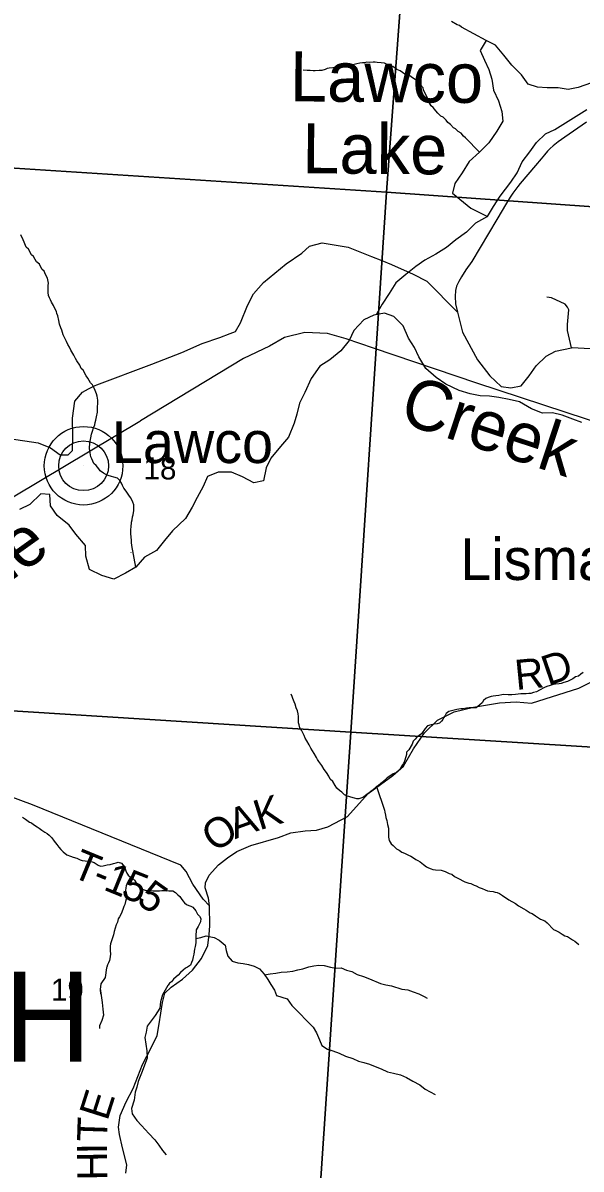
# Model space of a CAD drawing. Extents: x 0 to 34, y 0 to 22.
# Drawn here: x 6.769 to 7.827, y 16.547 to 18.72 of the extents above; entities that cross this region are included whole.
import ezdxf

# ---------------------------------------------------------------- set-up
doc = ezdxf.new("R2010")
doc.units = 0
for name, color, linetype in [('GM_X_County_Road', 7, 'Continuous'), ('GM_X_County_Road_Text', 7, 'Continuous'), ('GM_X_Minor_Lake', 7, 'Continuous'), ('GM_X_Minor_Lake_Text', 7, 'Continuous'), ('GM_X_Minor_River', 7, 'Continuous'), ('GM_X_Minor_River_Text', 7, 'Continuous'), ('GM_X_Rail_Line', 7, 'Continuous'), ('GM_X_Section', 7, 'Continuous'), ('GM_X_Section_Text', 7, 'Continuous'), ('GM_X_State_Route', 7, 'Continuous'), ('GM_X_Township_Road', 7, 'Continuous'), ('GM_X_Township_Road_Text', 7, 'Continuous'), ('GM_X_Township_Text', 7, 'Continuous'), ('GM_X_Unincorporated', 7, 'Continuous'), ('GM_X_Unincorporated_Location', 7, 'Continuous'), ('GM_X_Unincorporated_Text', 7, 'Continuous')]:
    doc.layers.add(name, color=color, linetype=linetype)

msp = doc.modelspace()

# ---------------------------------------------------------------- linework, layer by layer
at = {"layer": 'GM_X_County_Road'}
for points in [[(6.9065, 18.0325), (6.9091, 18.0338), (7.0137, 18.0729), (7.0705, 18.095), (7.1092, 18.112), (7.1425, 18.1234), (7.1622, 18.1306), (7.1721, 18.1348), (7.1816, 18.1511), (7.1948, 18.1841), (7.2062, 18.2058), (7.2251, 18.2278), (7.2679, 18.2627), (7.2979, 18.2832), (7.3123, 18.2965), (7.3362, 18.3029), (7.3858, 18.2946), (7.4299, 18.2768), (7.4492, 18.269)], [(7.4492, 18.269), (7.4677, 18.2616), (7.5086, 18.2434), (7.5344, 18.2298), (7.5925, 18.1713)], [(6.7435, 17.9318), (6.7985, 17.9234), (6.8216, 17.9139), (6.8402, 17.901), (6.8553, 17.9007), (6.8633, 17.9094), (6.864, 17.9367), (6.8633, 17.9701), (6.8678, 18.0027), (6.8822, 18.0198), (6.8935, 18.0257), (6.9065, 18.0325)], [(7.6306, 17.424), (7.672, 17.4307), (7.7035, 17.4327), (7.7327, 17.4304), (7.8225, 17.4585), (7.896, 17.4953), (7.9597, 17.5306), (7.9869, 17.5587), (8.0441, 17.6573), (8.0533, 17.6625)], [(6.9645, 16.5396), (6.9662, 16.5551), (6.958, 16.5874), (6.9525, 16.6129), (6.9507, 16.6266), (6.9535, 16.6486), (6.965, 16.6747), (6.9785, 16.7001), (6.9958, 16.7456), (7.012, 16.777), (7.0239, 16.8001), (7.0274, 16.8224), (7.0335, 16.8626), (7.0379, 16.8808), (7.0502, 16.8922), (7.0714, 16.907), (7.0906, 16.9242), (7.1079, 16.9464), (7.1194, 16.9711), (7.1224, 16.9916), (7.1234, 17.0081), (7.1226, 17.046), (7.1207, 17.0608), (7.1148, 17.08), (7.1155, 17.0899), (7.1221, 17.1044), (7.1401, 17.1236), (7.1571, 17.1372), (7.1743, 17.1492), (7.2012, 17.1603), (7.2536, 17.1755), (7.2768, 17.1843), (7.3039, 17.1883), (7.3255, 17.1897), (7.3472, 17.1957), (7.3841, 17.2155), (7.4231, 17.2588), (7.4701, 17.2933), (7.4902, 17.3108), (7.5091, 17.3438), (7.5303, 17.3738), (7.5549, 17.3977), (7.5864, 17.414), (7.6228, 17.4228), (7.6267, 17.4234), (7.6306, 17.424)]]:
    msp.add_lwpolyline(points, dxfattribs=at)
at = {"layer": 'GM_X_Minor_Lake'}
for points in [[(7.8464, 18.6061), (7.8213, 18.5971), (7.8024, 18.5934), (7.7834, 18.5965), (7.7622, 18.5966), (7.744, 18.5975), (7.7267, 18.6036), (7.7139, 18.6212), (7.6958, 18.6395), (7.6807, 18.6585), (7.6649, 18.6776), (7.6468, 18.686), (7.6353, 18.6671), (7.6435, 18.6488), (7.6518, 18.6313), (7.6578, 18.6131), (7.6607, 18.5918), (7.6704, 18.572), (7.6764, 18.5515), (7.6786, 18.5333), (7.6671, 18.5143), (7.6519, 18.4924), (7.6343, 18.4743), (7.6146, 18.4569), (7.6016, 18.4357), (7.5878, 18.4153), (7.5832, 18.3971), (7.618, 18.3682), (7.6496, 18.3527)], [(7.777, 18.5176), (7.8378, 18.5553)], [(7.6496, 18.3527), (7.6611, 18.3716), (7.6733, 18.3913), (7.6939, 18.4178), (7.7054, 18.4352), (7.7153, 18.4564), (7.7298, 18.4753), (7.742, 18.4927), (7.7595, 18.5094), (7.777, 18.5176)]]:
    msp.add_lwpolyline(points, dxfattribs=at)
at = {"layer": 'GM_X_Minor_River'}
for points in [[(7.6468, 18.686), (7.6003, 18.7118), (7.5966, 18.7149), (7.5917, 18.7161), (7.5815, 18.7223)], [(7.6343, 18.4743), (7.6078, 18.502), (7.604, 18.5047), (7.5995, 18.5104), (7.5939, 18.5139), (7.5886, 18.5186), (7.5849, 18.5209), (7.5792, 18.5267), (7.574, 18.5309), (7.571, 18.5355), (7.5654, 18.5409), (7.5612, 18.5428), (7.5556, 18.5482), (7.5518, 18.5528), (7.5466, 18.5594), (7.5428, 18.5624), (7.5391, 18.5686), (7.5369, 18.5743), (7.5343, 18.58), (7.5306, 18.5869), (7.5284, 18.5926), (7.5273, 18.5965), (7.5228, 18.6022), (7.5206, 18.606), (7.5153, 18.6103), (7.5093, 18.6142), (7.5003, 18.6204), (7.4931, 18.6227), (7.484, 18.6285), (7.4776, 18.6313), (7.4701, 18.6367), (7.4637, 18.6391), (7.4546, 18.643), (7.4478, 18.6438), (7.4406, 18.6447), (7.4364, 18.6451), (7.4326, 18.6451), (7.4262, 18.6448), (7.4209, 18.6449), (7.4167, 18.6442), (7.4125, 18.6439), (7.4076, 18.6432), (7.4019, 18.6421), (7.3946, 18.6403), (7.3893, 18.6392), (7.3821, 18.6382), (7.3779, 18.6375), (7.3673, 18.6361), (7.362, 18.635), (7.3566, 18.6347), (7.3498, 18.6336), (7.346, 18.6329), (7.3418, 18.6311), (7.3353, 18.6296), (7.3308, 18.6293), (7.3232, 18.6287), (7.319, 18.6287), (7.3137, 18.6292), (7.3076, 18.6292), (7.3004, 18.6297)], [(7.6496, 18.3527), (7.6269, 18.3403), (7.6098, 18.323), (7.5892, 18.3083), (7.572, 18.2939), (7.5515, 18.2811), (7.5305, 18.2698), (7.5134, 18.2581), (7.4947, 18.243), (7.4756, 18.2272), (7.4634, 18.2064), (7.4496, 18.1863), (7.4396, 18.1689), (7.4391, 18.1668)], [(6.7697, 18.3081), (6.7653, 18.3177)], [(6.9829, 17.689), (6.9832, 17.6883), (6.9755, 17.7291), (6.9752, 17.7348), (6.9753, 17.7398), (6.9745, 17.744), (6.9739, 17.7527), (6.974, 17.7599), (6.9744, 17.7641), (6.9753, 17.7736), (6.9761, 17.7774), (6.9769, 17.7834), (6.9781, 17.7872), (6.9793, 17.7952), (6.9797, 17.7994), (6.9794, 17.8062), (6.9776, 17.8112), (6.9754, 17.8158), (6.9731, 17.82), (6.9698, 17.8242), (6.9649, 17.8319), (6.9605, 17.838), (6.9579, 17.8426), (6.956, 17.8472), (6.953, 17.8525), (6.9485, 17.8568), (6.9417, 17.8587), (6.9372, 17.8596), (6.9311, 17.8619), (6.9274, 17.8631), (6.9217, 17.8662), (6.9157, 17.8705), (6.9131, 17.8743), (6.9078, 17.8808), (6.9037, 17.8843), (6.9, 17.8935), (6.8978, 17.8973), (6.8964, 17.9083), (6.8957, 17.9129), (6.8962, 17.9239), (6.8982, 17.933), (6.8994, 17.9398), (6.901, 17.9455), (6.903, 17.9523), (6.9053, 17.958), (6.9065, 17.9625), (6.9077, 17.9667), (6.9085, 17.9731), (6.9105, 17.9815), (6.9109, 17.9857), (6.9112, 18.0043), (6.9101, 18.0123), (6.9086, 18.0165), (6.9064, 18.0229), (6.9046, 18.0275), (6.9009, 18.0337), (6.8975, 18.0375), (6.8923, 18.0463), (6.8889, 18.0505), (6.8837, 18.0612), (6.88, 18.0647), (6.877, 18.0708), (6.8714, 18.0792), (6.8688, 18.0838), (6.8659, 18.0899), (6.8603, 18.0991), (6.8573, 18.1049), (6.8543, 18.1102), (6.8521, 18.116), (6.848, 18.1232), (6.8454, 18.1282), (6.8429, 18.1374), (6.841, 18.1416), (6.8389, 18.1488), (6.8374, 18.1553), (6.8352, 18.1644), (6.8334, 18.169), (6.8327, 18.1728), (6.829, 18.1793), (6.8271, 18.1839), (6.8238, 18.1904), (6.8215, 18.1946), (6.8197, 18.1984), (6.8178, 18.2026), (6.8172, 18.2084), (6.8173, 18.222), (6.8177, 18.2262), (6.816, 18.2357), (6.8122, 18.243), (6.8097, 18.2491), (6.8059, 18.2522), (6.8033, 18.2564), (6.8007, 18.2621), (6.7954, 18.2668), (6.7925, 18.2714), (6.7891, 18.2767), (6.7854, 18.2802), (6.7802, 18.2905), (6.7757, 18.2944), (6.7716, 18.3043), (6.7697, 18.3081)], [(7.8284, 17.9623), (7.811, 17.9684), (7.791, 17.9761), (7.7724, 17.9804), (7.7539, 17.9801), (7.733, 17.9878), (7.71, 18.0012), (7.6907, 18.0055), (7.6706, 18.0094), (7.6532, 18.0118), (7.6358, 18.013), (7.6164, 18.0165), (7.596, 18.0227), (7.5707, 18.035), (7.5522, 18.0476), (7.5326, 18.0644), (7.5191, 18.0869), (7.5112, 18.1044), (7.4996, 18.1219), (7.4895, 18.1455), (7.4722, 18.163), (7.4544, 18.1696), (7.4339, 18.1659), (7.4149, 18.1565), (7.3965, 18.1368), (7.3873, 18.1175), (7.3716, 18.0982), (7.3506, 18.0809), (7.332, 18.0692), (7.3155, 18.0457), (7.3036, 18.0192), (7.2932, 17.9988), (7.2881, 17.9783), (7.2835, 17.9612), (7.2723, 17.9347), (7.257, 17.9166), (7.2387, 17.8946), (7.2302, 17.8765), (7.2251, 17.8514), (7.2069, 17.8477), (7.1853, 17.8592), (7.1642, 17.8681), (7.1395, 17.8682), (7.119, 17.8599), (7.1105, 17.841), (7.0997, 17.8198), (7.0898, 17.802), (7.0775, 17.78), (7.0527, 17.7566), (7.0374, 17.7385), (7.0225, 17.7199), (6.9996, 17.7072), (6.9832, 17.6883), (6.9638, 17.6766), (6.9417, 17.6653), (6.9186, 17.6719), (6.8956, 17.6834), (6.8885, 17.7089), (6.8879, 17.729), (6.8698, 17.7504), (6.8571, 17.7679), (6.8344, 17.7862), (6.8213, 17.8041), (6.8203, 17.8258), (6.8032, 17.827), (6.7822, 17.8066), (6.7628, 17.7972)], [(6.9735, 17.7159), (6.9736, 17.7154)], [(7.8306, 17.4885), (7.826, 17.4852), (7.8217, 17.4814), (7.8164, 17.48), (7.8114, 17.4762), (7.8008, 17.471), (7.7939, 17.4692), (7.7893, 17.4674), (7.7852, 17.4671), (7.7783, 17.466), (7.7741, 17.4653), (7.768, 17.4639), (7.7616, 17.462), (7.7574, 17.4598), (7.7482, 17.4546), (7.7421, 17.4516), (7.7364, 17.4502), (7.7314, 17.4484), (7.7277, 17.4484), (7.7227, 17.4477), (7.7166, 17.4478), (7.7125, 17.4478), (7.7026, 17.4468), (7.6958, 17.4461), (7.6889, 17.4462), (7.6806, 17.4467), (7.6764, 17.446), (7.6707, 17.4449), (7.6654, 17.4442), (7.6604, 17.4432), (7.6566, 17.4428), (7.6505, 17.441), (7.6464, 17.4392), (7.6421, 17.435), (7.6394, 17.4309), (7.6348, 17.4268), (7.6279, 17.4215), (7.6226, 17.4216), (7.6147, 17.4213), (7.6097, 17.4206), (7.6029, 17.4196), (7.5987, 17.4192), (7.5915, 17.4182), (7.5865, 17.4171), (7.5812, 17.416), (7.5763, 17.4142), (7.5709, 17.4109), (7.569, 17.4071), (7.5666, 17.4033), (7.5647, 17.3995), (7.5624, 17.3958), (7.5582, 17.3924), (7.5544, 17.3913), (7.5487, 17.3906), (7.543, 17.3892), (7.5357, 17.3874), (7.5315, 17.3825), (7.5246, 17.3723), (7.5154, 17.366), (7.5127, 17.3622), (7.5088, 17.3584), (7.5065, 17.3524), (7.5007, 17.3418), (7.4957, 17.3373), (7.496, 17.3331), (7.4945, 17.3282), (7.4925, 17.3206), (7.4905, 17.3157), (7.487, 17.3116), (7.4839, 17.3059), (7.4759, 17.2984), (7.4709, 17.2962), (7.4644, 17.2917), (7.4595, 17.2888), (7.4506, 17.2805), (7.443, 17.2742), (7.4392, 17.2723)], [(7.4392, 17.2723), (7.4311, 17.2644), (7.4254, 17.2603), (7.4208, 17.2573), (7.415, 17.2525), (7.4112, 17.251), (7.4055, 17.2492), (7.4017, 17.2488), (7.3972, 17.25), (7.3908, 17.252), (7.387, 17.2532), (7.3832, 17.254), (7.3783, 17.2567), (7.3734, 17.2613), (7.3689, 17.2648), (7.364, 17.2691), (7.3607, 17.2744), (7.3562, 17.2817), (7.3517, 17.2863), (7.3487, 17.2921), (7.3446, 17.2986), (7.3401, 17.3043), (7.3357, 17.3124), (7.3301, 17.3196), (7.3275, 17.3235), (7.3252, 17.3273), (7.3211, 17.3346), (7.3178, 17.3396), (7.3148, 17.3449), (7.3115, 17.3514), (7.307, 17.3587), (7.304, 17.364), (7.3022, 17.369), (7.2974, 17.3789), (7.294, 17.3835), (7.2926, 17.3893), (7.2915, 17.3931), (7.2912, 17.3999), (7.2912, 17.4052), (7.2905, 17.4102), (7.2895, 17.4159), (7.2872, 17.4216), (7.285, 17.4285), (7.2832, 17.4327), (7.2806, 17.4392), (7.2791, 17.443), (7.2777, 17.4476)], [(7.4392, 17.2723), (7.4542, 17.2277), (7.4549, 17.2239), (7.456, 17.2178), (7.4571, 17.2136), (7.4585, 17.2078), (7.4603, 17.2002), (7.4618, 17.193), (7.4617, 17.1877), (7.4617, 17.1827), (7.462, 17.1763), (7.4634, 17.1698), (7.4671, 17.1637), (7.4709, 17.1606), (7.4769, 17.1544), (7.4818, 17.1513), (7.4871, 17.1478), (7.4923, 17.1459), (7.4995, 17.142), (7.504, 17.1404), (7.5093, 17.1369), (7.5135, 17.1342), (7.5176, 17.1323), (7.5221, 17.1292), (7.5285, 17.1245), (7.5338, 17.1203), (7.5376, 17.118), (7.5425, 17.1164), (7.5462, 17.1148), (7.5508, 17.1144), (7.5614, 17.1135), (7.5693, 17.1111), (7.5769, 17.1072), (7.5818, 17.106), (7.5871, 17.1018), (7.5969, 17.0967), (7.6025, 17.0932), (7.6067, 17.0916), (7.6142, 17.0893), (7.618, 17.0885), (7.6241, 17.0853), (7.6282, 17.0841), (7.6335, 17.0807), (7.6392, 17.0787), (7.6448, 17.0763), (7.6497, 17.0744), (7.6539, 17.0736), (7.66, 17.0735), (7.6637, 17.0719), (7.6679, 17.0711), (7.6721, 17.0692), (7.6777, 17.0657), (7.6897, 17.0572), (7.7022, 17.0505), (7.7082, 17.0463), (7.718, 17.0405), (7.7225, 17.0378), (7.7301, 17.0331), (7.7342, 17.0315), (7.7406, 17.0269), (7.75, 17.0211), (7.758, 17.0176), (7.7625, 17.0137), (7.7745, 17.0014), (7.779, 16.9994), (7.785, 16.9959), (7.7911, 16.9921), (7.796, 16.9893), (7.8009, 16.9878), (7.8065, 16.9843), (7.8107, 16.9816), (7.8152, 16.9792), (7.8227, 16.9726)], [(6.7685, 17.2139), (6.7745, 17.2104), (6.782, 17.2046), (6.7858, 17.2034), (6.7896, 17.2003), (6.7964, 17.1961), (6.8001, 17.193), (6.805, 17.1895), (6.8107, 17.1856), (6.8152, 17.1829), (6.8189, 17.1802), (6.8242, 17.1748), (6.8283, 17.1687), (6.8335, 17.1622), (6.8373, 17.1575), (6.841, 17.1526), (6.8455, 17.1487), (6.8527, 17.1425), (6.8598, 17.1405), (6.8644, 17.1386), (6.8716, 17.1362), (6.8776, 17.1331), (6.8817, 17.1323), (6.8874, 17.1315), (6.8939, 17.1306), (6.9003, 17.1294), (6.9045, 17.1282), (6.9082, 17.1255), (6.912, 17.1232), (6.9165, 17.1216), (6.9211, 17.1219), (6.9291, 17.1237), (6.9344, 17.1244), (6.9412, 17.1266), (6.9458, 17.1277), (6.9496, 17.1288), (6.956, 17.1272), (6.962, 17.1203), (6.9646, 17.1122), (6.9665, 17.108), (6.9687, 17.1042), (6.9732, 17.1004), (6.977, 17.0984), (6.9807, 17.0946), (6.9841, 17.09), (6.9878, 17.0857), (6.9916, 17.0807), (6.9953, 17.078), (7.001, 17.0757), (7.0074, 17.0752), (7.0154, 17.0744), (7.0283, 17.0746), (7.0328, 17.0749), (7.037, 17.0752), (7.0457, 17.0747), (7.0533, 17.0743), (7.0582, 17.0715), (7.0627, 17.0669), (7.0665, 17.0638), (7.0691, 17.06), (7.0721, 17.0558), (7.0754, 17.052), (7.0792, 17.0489), (7.0837, 17.0469), (7.0875, 17.0453), (7.0913, 17.0434), (7.0969, 17.0365), (7.0999, 17.03), (7.1036, 17.0265), (7.1062, 17.0223), (7.1058, 17.0155), (7.1015, 17.0068), (7.0976, 17.0004), (7.0967, 16.9886), (7.097, 16.9821), (7.0969, 16.9757), (7.0957, 16.9692), (7.0945, 16.9639), (7.0933, 16.9548), (7.0921, 16.9492), (7.0909, 16.9431)], [(6.9732, 17.1004), (6.9666, 17.089), (6.965, 17.0841), (6.9642, 17.08), (6.9638, 17.0754), (6.9637, 17.0689), (6.9641, 17.0648), (6.9647, 17.059), (6.9639, 17.0545), (6.9627, 17.0488), (6.9604, 17.0447), (6.9585, 17.0394), (6.9553, 17.0311), (6.9522, 17.025), (6.9499, 17.0212), (6.9483, 17.0152), (6.9463, 17.0099), (6.942, 16.9974), (6.9408, 16.9913), (6.9389, 16.9857), (6.9369, 16.9796), (6.9353, 16.9739), (6.9345, 16.9694), (6.9345, 16.9656), (6.9348, 16.961), (6.9351, 16.9549), (6.9347, 16.9496), (6.9334, 16.9428), (6.9315, 16.9383), (6.9299, 16.9345), (6.9284, 16.93), (6.9279, 16.9288)], [(7.0969, 16.9842), (7.1066, 16.9858), (7.1165, 16.9891), (7.1316, 16.986), (7.1414, 16.9813), (7.1523, 16.9718), (7.1541, 16.9615), (7.1575, 16.9505), (7.1657, 16.941), (7.1763, 16.9379), (7.1865, 16.9366), (7.1964, 16.9347), (7.2073, 16.9316), (7.2175, 16.9269), (7.2265, 16.9163), (7.2333, 16.9067), (7.2393, 16.8968), (7.246, 16.8862), (7.2498, 16.8763), (7.2509, 16.8751)], [(6.9279, 16.9288), (6.925, 16.9104), (6.917, 16.8983), (6.9158, 16.8877), (6.9165, 16.8789)], [(7.0909, 16.9431), (7.0889, 16.9386), (7.0866, 16.9336), (7.0812, 16.9299), (7.0774, 16.9277), (7.0728, 16.9239), (7.0679, 16.9198), (7.0632, 16.9149), (7.0594, 16.9116), (7.0548, 16.9071), (7.051, 16.9022), (7.0471, 16.8996), (7.0444, 16.8958), (7.0437, 16.8949)], [(7.2272, 16.9154), (7.2375, 16.917), (7.2485, 16.9188), (7.2584, 16.9202), (7.2701, 16.9213), (7.2804, 16.922), (7.2899, 16.9249), (7.2997, 16.9268), (7.3107, 16.9305), (7.3202, 16.9323), (7.3297, 16.9334), (7.3403, 16.9329), (7.352, 16.9298), (7.3622, 16.9282), (7.3721, 16.9289), (7.3823, 16.9239), (7.3925, 16.9216), (7.4027, 16.9162), (7.4144, 16.9123), (7.4257, 16.9077), (7.4469, 16.8992), (7.4571, 16.8965), (7.4673, 16.8942), (7.4869, 16.888), (7.4987, 16.8871), (7.5089, 16.8833), (7.5194, 16.8794), (7.5292, 16.874), (7.5349, 16.8709)], [(6.916, 16.8895), (6.9194, 16.8626), (6.9208, 16.8504), (6.9223, 16.8391), (6.9189, 16.8288), (6.9147, 16.8186), (6.9143, 16.8133)], [(7.0437, 16.8949), (7.0337, 16.8773), (7.0302, 16.8641), (7.0287, 16.852), (7.02, 16.8383), (7.0048, 16.8179), (7.0028, 16.8065), (7.0002, 16.7963), (7.002, 16.7838), (7.0043, 16.7713), (7.0046, 16.7576), (6.9997, 16.744), (6.9955, 16.7322), (6.9878, 16.7133), (6.9852, 16.7027), (6.9821, 16.6932), (6.9798, 16.6777), (6.9752, 16.6618), (6.976, 16.6519), (6.985, 16.6394), (6.9941, 16.6298), (7.008, 16.6146), (7.019, 16.6028), (7.0269, 16.5926), (7.0337, 16.5823), (7.0405, 16.5739)], [(7.2498, 16.8763), (7.2702, 16.8697), (7.2789, 16.8575), (7.2932, 16.8427), (7.3064, 16.829), (7.3189, 16.8164), (7.3257, 16.8054), (7.3309, 16.7921), (7.3355, 16.7815), (7.3464, 16.7742), (7.3563, 16.7715), (7.3684, 16.7669), (7.3804, 16.7612), (7.3941, 16.7566), (7.405, 16.7516), (7.4152, 16.749), (7.4258, 16.7459), (7.4368, 16.7417), (7.4481, 16.7371), (7.4599, 16.7317), (7.4712, 16.7287), (7.4848, 16.726), (7.4958, 16.7206), (7.5079, 16.7141), (7.5211, 16.7069), (7.5313, 16.6989), (7.5411, 16.6935), (7.5502, 16.6886)]]:
    msp.add_lwpolyline(points, dxfattribs=at)
at = {"layer": 'GM_X_Rail_Line'}
msp.add_lwpolyline([(8.0084, 17.842), (8.0071, 17.8786), (7.997, 17.8973), (7.9816, 17.917), (7.9641, 17.927), (7.6293, 18.0366), (7.4337, 18.1028), (7.3817, 18.121), (7.3462, 18.1309), (7.3036, 18.1327), (7.2652, 18.1234), (7.2362, 18.1066), (7.1873, 18.0836), (6.9922, 17.9653), (6.9911, 17.9641), (6.4682, 17.6519)], dxfattribs=at)
at = {"layer": 'GM_X_Section'}
for points in [[(6.5282, 19.4822), (7.5335, 19.4104), (7.4583, 18.399), (6.4594, 18.4632)], [(7.5335, 19.4104), (8.5509, 19.3356), (8.4739, 18.3269), (7.4583, 18.399)], [(6.4594, 18.4632), (7.4583, 18.399), (7.3907, 17.3751), (6.388, 17.4386)], [(7.4583, 18.399), (8.4739, 18.3269), (8.3983, 17.3128), (7.3907, 17.3751)], [(6.388, 17.4386), (7.3907, 17.3751), (7.3221, 16.3607), (6.3205, 16.4222)], [(7.3907, 17.3751), (8.3983, 17.3128), (8.3308, 16.3019), (7.3221, 16.3607)]]:
    msp.add_lwpolyline(points, close=True, dxfattribs=at)
at = {"layer": 'GM_X_State_Route'}
msp.add_lwpolyline([(7.8368, 18.5312), (7.7957, 18.5032), (7.7832, 18.494), (7.7736, 18.4863), (7.768, 18.4813), (7.7631, 18.4764), (7.7572, 18.4698), (7.7509, 18.4619), (7.7405, 18.4492), (7.7113, 18.4149), (7.7067, 18.4098), (7.6973, 18.3969), (7.6923, 18.3893), (7.6853, 18.378), (7.6671, 18.3472), (7.6514, 18.3201), (7.6356, 18.2941), (7.62, 18.2674), (7.6083, 18.2514), (7.5999, 18.238), (7.595, 18.2295), (7.5908, 18.2207), (7.5891, 18.2124), (7.5882, 18.2013), (7.5891, 18.1869), (7.5925, 18.1713), (7.6024, 18.1333), (7.6307, 18.081), (7.6538, 18.0504), (7.6756, 18.0305), (7.6934, 18.0276), (7.7131, 18.032), (7.7284, 18.0508), (7.7419, 18.0696), (7.7606, 18.088), (7.7782, 18.0973), (7.8088, 18.104), (7.8097, 18.1042), (7.8437, 18.1024)], dxfattribs=at)
at = {"layer": 'GM_X_Township_Road'}
for points in [[(7.8088, 18.104), (7.8012, 18.1367), (7.801, 18.1479), (7.8035, 18.1758), (7.8013, 18.1808), (7.7964, 18.1864), (7.7708, 18.1983), (7.7616, 18.1996)], [(7.1226, 17.046), (7.1106, 17.0588), (7.0911, 17.0874), (7.0786, 17.1113), (7.0685, 17.1229), (6.7872, 17.2377), (6.7434, 17.2538)]]:
    msp.add_lwpolyline(points, dxfattribs=at)
at = {"layer": 'GM_X_Unincorporated'}
for radius in [0.0744, 0.0472]:
    msp.add_circle((6.8843, 17.8802), radius, dxfattribs=at)
at = {"layer": 'GM_X_Unincorporated_Location'}
msp.add_line((6.8843, 17.8802), (6.8843, 17.8802), dxfattribs=at)

# ---------------------------------------------------------------- texts
at = {"layer": 'GM_X_County_Road_Text'}
for s, rotation, p in [('R', 5.5762, (7.7038, 17.4552)), ('D', 18.8699, (7.764, 17.4627)), ('K', 17.4149, (7.2173, 17.189)), ('A', 19.8687, (7.1709, 17.1722)), ('O', 33.8093, (7.1326, 17.146)), ('E', 72.3572, (6.9292, 16.6369)), ('T', 88.1311, (6.9285, 16.5985)), ('I', 90.6791, (6.9288, 16.5758)), ('H', 90.8561, (6.9295, 16.5259))]:
    msp.add_text(s, height=0.0568, rotation=rotation, dxfattribs=at).set_placement(p)
at = {"layer": 'GM_X_Minor_Lake_Text'}
for s, rotation, p in [('Lawco', 359.4987, (7.2748, 18.571)), ('Lake', 359.4988, (7.2983, 18.4347))]:
    msp.add_text(s, height=0.0947, rotation=rotation, dxfattribs=at).set_placement(p)
at = {"layer": 'GM_X_Minor_River_Text'}
for s, rotation, p in [('Creek', 341.8119, (7.4788, 17.9636)), ('Pine', 35.4888, (6.6183, 17.57))]:
    msp.add_text(s, height=0.09469, rotation=rotation, dxfattribs=at).set_placement(p)
at = {"layer": 'GM_X_Section_Text'}
for s, p in [('18', (6.9979, 17.8542)), ('19', (6.8225, 16.8663))]:
    msp.add_text(s, height=0.04186, rotation=0, dxfattribs=at).set_placement(p)
at = {"layer": 'GM_X_Township_Road_Text'}
for s, rotation, p in [('T', 337.6801, (6.8588, 17.1025)), ('1', 337.829, (6.9198, 17.0774)), ('-', 337.7059, (6.8981, 17.0863)), ('5', 338.3535, (6.9527, 17.064)), ('5', 324.5156, (6.9821, 17.0528))]:
    msp.add_text(s, height=0.0568, rotation=rotation, dxfattribs=at).set_placement(p)
at = {"layer": 'GM_X_Township_Text'}
msp.add_text('ELIZABETH', height=0.17045, rotation=0, dxfattribs=at).set_placement((5.6574, 16.7509))
at = {"layer": 'GM_X_Unincorporated_Text'}
for s, p in [('Lawco', (6.9379, 17.8853)), ('Lisman', (7.5979, 17.6637))]:
    msp.add_text(s, height=0.07898, rotation=0, dxfattribs=at).set_placement(p)

doc.saveas('drawing.dxf')
